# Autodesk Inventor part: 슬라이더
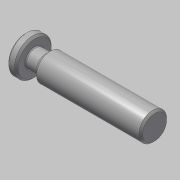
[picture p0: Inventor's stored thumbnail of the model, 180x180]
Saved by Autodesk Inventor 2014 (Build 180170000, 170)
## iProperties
Created: 2016-05
Part Number: 슬라이더
Document SubType Name: Modeling
Designer: mduedu
Density: 7.86 g/cm^3
Material: 강철, 연강
Appearance: Steel
Author: mduedu
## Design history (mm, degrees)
sketch "스케치1"
  geometry: L1 (-7.5, 0)-(62.5, 0); L2 (62.5, 0)-(62.5, 7.5); L3 (62.5, 7.5)-(0, 7.5); L4 (-7.5, 0)-(-7.5, 10); L5 (-7.5, 10)-(-2.5, 10); L6 (-2.5, 10)-(-2.5, 5); L7 (-2.5, 5)-(3.5, 5); L8 (3.5, 5)-(6, 7.5); A1 r 7.5 centre (0, 0) between (0, 7.5) and (-7.5, 0); 1 further point
  constraints: 16 end point, 3 perpendicular, 2 horizontal, 2 parallel, 2 point on circle, 2 point on line, 2 tangent, 1 centre point, 1 coincident
  dimensions: "d0" = 15 diameter of A1; "d1" = 70 distance of L1.start L1.end; "d19" = 20 diameter of L5 L1; "d20" = 10 diameter of L7 L1; "d21" = 5 distance of L4.end L5.end; "d22" = 135 deg angle of L8 L7; "d23" = 6 distance of L6.end L7.end
revolve "회전1" stored, may be unused: angle "d4" = 90 deg
chamfer "모따기2" distance "d24" = 1; stored, may be unused: second distance "d25" = 2, angle "d26" = 45 deg
fillet "모깎기1" dims "d27" = 0.5
node "솔리드1"
